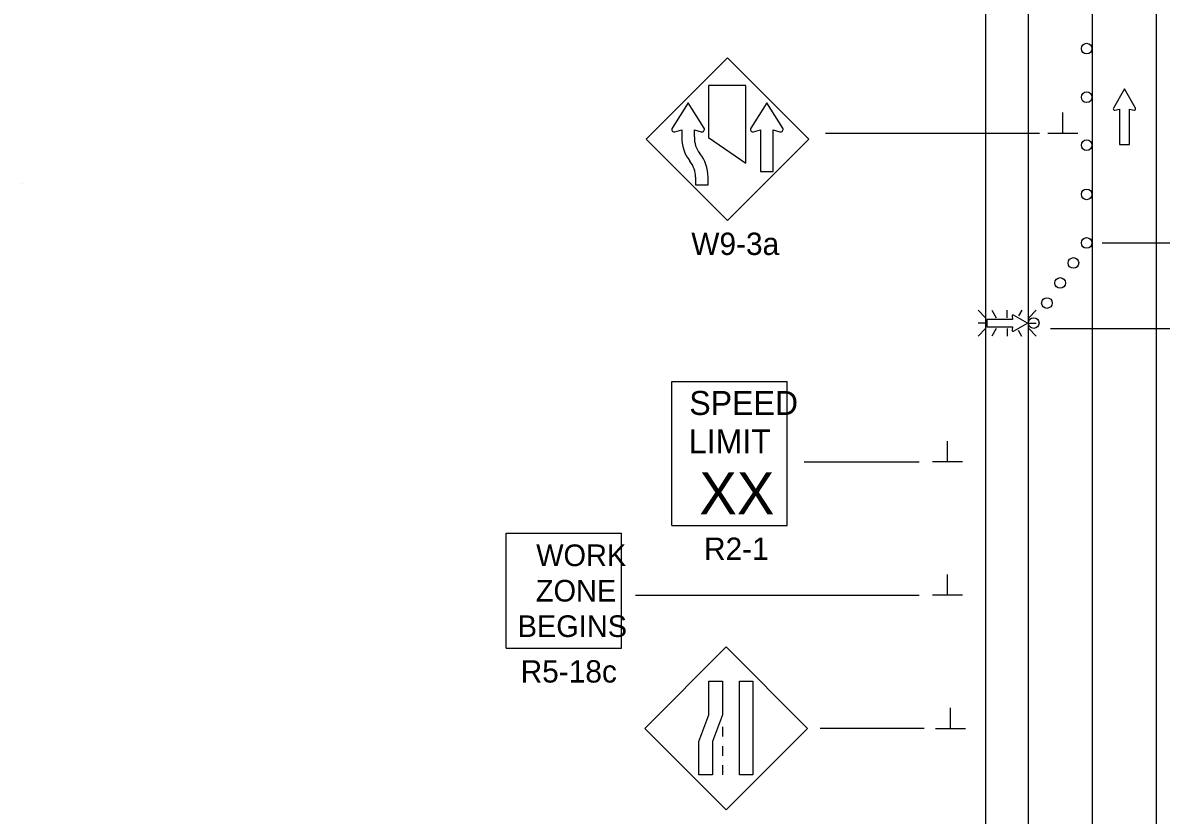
# Model space of a CAD drawing. Extents: x 16595 to 19519, y 6994 to 8256.
# Drawn here: x 16594.8 to 17021.9, y 7591.8 to 7888.9 of the extents above; entities that cross this region are included whole.
import ezdxf

# ---------------------------------------------------------------- set-up
doc = ezdxf.new("R2010")
doc.units = 0
for name, color, linetype in [('ALI_LEGAL_EX', 7, 'Continuous'), ('MT_SCRATCH_LEVEL_E', 7, 'Continuous'), ('PAVT_EDGE_EX', 7, 'Continuous'), ('TRAFFIC_SIGNS_PR', 7, 'Continuous'), ('TYPICAL_TEXT_DIMEN_PR', 7, 'Continuous')]:
    doc.layers.add(name, color=color, linetype=linetype)

msp = doc.modelspace()

# ---------------------------------------------------------------- linework, layer by layer
at = {"layer": 'ALI_LEGAL_EX'}
for p, q in [((16995.95, 8243.16), (16995.95, 7425.02)), ((17019.95, 8243.16), (17019.95, 7425.02))]:
    msp.add_line(p, q, dxfattribs=at)
for points in [[(17019.95, 7824.26), (17019.95, 7799.26)], [(16995.95, 7724.26), (16995.95, 7699.26)], [(17019.95, 7724.26), (17019.95, 7699.26)], [(16995.95, 7624.26), (16995.95, 7599.26)], [(17019.95, 7624.26), (17019.95, 7599.26)]]:
    msp.add_lwpolyline(points, dxfattribs=at)
at = {"layer": 'MT_SCRATCH_LEVEL_E'}
for p, q in [((17008.06, 7864.11), (17003.94, 7856.86)), ((17012.2, 7856.86), (17008.06, 7864.11)), ((17004.43, 7856.18), (17006.2, 7856.5)), ((17006.2, 7856.5), (17006.2, 7843.24)), ((17009.94, 7843.24), (17009.94, 7856.5)), ((17009.94, 7856.5), (17011.72, 7856.18)), ((17006.2, 7843.24), (17009.94, 7843.24))]:
    msp.add_line(p, q, dxfattribs=at)
for centre, start, end in [((17004.35, 7856.64), 150.4248, 279.9638), ((17011.79, 7856.64), 260.0362, 29.7731)]:
    msp.add_arc(centre, 0.463, start, end, dxfattribs=at)
at = {"layer": 'PAVT_EDGE_EX'}
for p, q in [((16955.95, 8212.14), (16955.95, 7351.67)), ((16971.95, 8212.14), (16971.95, 7351.67))]:
    msp.add_line(p, q, dxfattribs=at)
at = {"layer": 'TRAFFIC_SIGNS_PR'}
for p, q in [((16859.14, 7875.83), (16828.6, 7845.29)), ((16889.69, 7845.29), (16859.14, 7875.83)), ((16828.6, 7845.29), (16859.14, 7814.74)), ((16859.14, 7814.74), (16889.69, 7845.29)), ((16955.97, 7778.35), (16953.15, 7781.17)), ((16958.26, 7781.17), (16959.89, 7778.35)), ((16964.05, 7778.35), (16964.05, 7781.17)), ((16969.52, 7781.17), (16968.31, 7779.07)), ((16974.96, 7781.17), (16972.14, 7778.35)), ((16955.97, 7776.32), (16953.15, 7776.32)), ((16955.97, 7774.28), (16953.15, 7771.46)), ((16959.92, 7774.28), (16958.29, 7771.46)), ((16964.05, 7774.28), (16964.05, 7771.46)), ((16968.24, 7773.65), (16969.5, 7771.46)), ((16972.14, 7776.32), (16974.96, 7776.32)), ((16974.96, 7771.47), (16972.14, 7774.28)), ((16838.33, 7754.41), (16881.53, 7754.41)), ((16838.33, 7700.41), (16838.33, 7754.41)), ((16881.53, 7700.41), (16881.53, 7754.41)), ((16838.33, 7700.41), (16881.53, 7700.41)), ((16776.14, 7654.41), (16776.14, 7697.61)), ((16776.14, 7697.61), (16819.34, 7697.61)), ((16819.34, 7654.41), (16819.34, 7697.61)), ((16776.14, 7654.41), (16819.34, 7654.41)), ((16858.67, 7654.9), (16828.12, 7624.36)), ((16889.22, 7624.36), (16858.67, 7654.9)), ((16828.12, 7624.36), (16858.67, 7593.81)), ((16857.27, 7624.91), (16857.27, 7621.31)), ((16858.67, 7593.81), (16889.22, 7624.36)), ((16857.27, 7617.71), (16857.27, 7614.11)), ((16857.27, 7610.51), (16857.27, 7606.91))]:
    msp.add_line(p, q, dxfattribs=at)
for points in [[(16852.04, 7865.46), (16852.04, 7845.95), (16866, 7836.25), (16866, 7865.46)], [(16857.27, 7642.06), (16857.27, 7629.48), (16853.5, 7619.49), (16853.5, 7606.91), (16848.45, 7606.91), (16848.45, 7619.49), (16852.21, 7629.48), (16852.21, 7642.06)], [(16868.67, 7642.06), (16868.67, 7606.91), (16863.61, 7606.91), (16863.61, 7642.06)]]:
    msp.add_lwpolyline(points, close=True, dxfattribs=at)
for points in [[(16850.36, 7849.46), (16844.36, 7858.87), (16838.37, 7849.45)], [(16879.86, 7849.45), (16873.87, 7858.87), (16867.88, 7849.45)], [(16839.42, 7848.04), (16842, 7848.74), (16842, 7846.23)], [(16846.72, 7846.12), (16846.72, 7848.74), (16849.31, 7848.04)], [(16868.93, 7848.03), (16871.51, 7848.74), (16871.51, 7833.22), (16876.23, 7833.22), (16876.23, 7848.74), (16878.82, 7848.04)], [(16847.14, 7831.1), (16847.14, 7828.12), (16851.86, 7828.12), (16851.86, 7831.1)], [(16965.88, 7779), (16966.11, 7777.7), (16956.39, 7777.7), (16956.39, 7774.96), (16966.11, 7774.96), (16965.88, 7773.65)], [(16966.38, 7773.3), (16971.69, 7776.32), (16966.38, 7779.36)]]:
    msp.add_lwpolyline(points, dxfattribs=at)
for centre in [(16993.89, 7879.24), (16993.89, 7861.02), (16993.89, 7843.03), (16993.89, 7824.6), (16993.89, 7806.38), (16988.92, 7798.87), (16983.95, 7791.37), (16978.98, 7783.86), (16974.01, 7776.36)]:
    msp.add_circle(centre, 2, dxfattribs=at)
for centre, radius, start, end in [((16839.17, 7848.95), 0.945, 147.5204, 285.3986), ((16856.16, 7845.82), 14.17, 178.3293, 218.5427), ((16856.16, 7845.82), 9.45, 178.1936, 218.5465), ((16834.91, 7846.49), 11.81, 358.1894, 0.0048), ((16849.56, 7848.95), 0.947, 254.6828, 32.2708), ((16846.19, 7836.64), 11.81, 74.68, 74.6808), ((16860.32, 7855.79), 11.81, 212.4569, 212.4665), ((16868.68, 7848.95), 0.946, 147.5497, 285.3316), ((16879.07, 7848.95), 0.943, 254.6778, 32.4665), ((16889.83, 7855.79), 11.81, 212.4569, 212.4665), ((16837.69, 7831.1), 9.45, 0, 38.5457), ((16837.69, 7831.1), 14.17, 0, 38.5422), ((16604.75, 7834.9), 11.81, 212.4569, 212.4665), ((16966.22, 7779.06), 0.341, 61.4833, 189.9593), ((16966.21, 7773.6), 0.341, 170.7308, 298.8916)]:
    msp.add_arc(centre, radius, start, end, dxfattribs=at)
at = {"layer": 'TYPICAL_TEXT_DIMEN_PR'}
for p, q in [((16984.99, 7847.45), (16984.99, 7855.24)), ((16976.16, 7847.45), (16895.88, 7847.45)), ((16990.62, 7847.45), (16979.37, 7847.45)), ((16999.7, 7806.38), (17143.76, 7806.38)), ((16980.35, 7774.28), (17108.95, 7774.28)), ((16941.7, 7724.28), (16941.7, 7732.06)), ((16887.91, 7724.28), (16931.01, 7724.28)), ((16947.33, 7724.28), (16936.08, 7724.28)), ((16941.7, 7674.28), (16941.7, 7682.06)), ((16824.67, 7674.28), (16931.01, 7674.28)), ((16947.33, 7674.28), (16936.08, 7674.28)), ((16942.82, 7624.28), (16942.82, 7632.06)), ((16932.95, 7624.28), (16893.95, 7624.28)), ((16937.2, 7624.28), (16948.45, 7624.28))]:
    msp.add_line(p, q, dxfattribs=at)

# ---------------------------------------------------------------- texts
at = {"layer": 'TRAFFIC_SIGNS_PR'}
for s, height, p in [('W9-3a', 8.37, (16845.57, 7801.87)), ('SPEED', 9, (16844.82, 7741.88)), ('LIMIT', 9, (16844.64, 7727.48)), ('XX', 15.785, (16848.58, 7704.64)), ('R2-1', 8.37, (16850.34, 7687.54)), ('WORK', 8.119, (16787.39, 7685.2)), ('ZONE', 8.119, (16787.26, 7671.91)), ('BEGINS', 8.119, (16780.43, 7658.62)), ('R5-18c', 8.37, (16781.56, 7641.54))]:
    msp.add_text(s, height=height, dxfattribs=at).set_placement(p)

doc.saveas('drawing.dxf')
